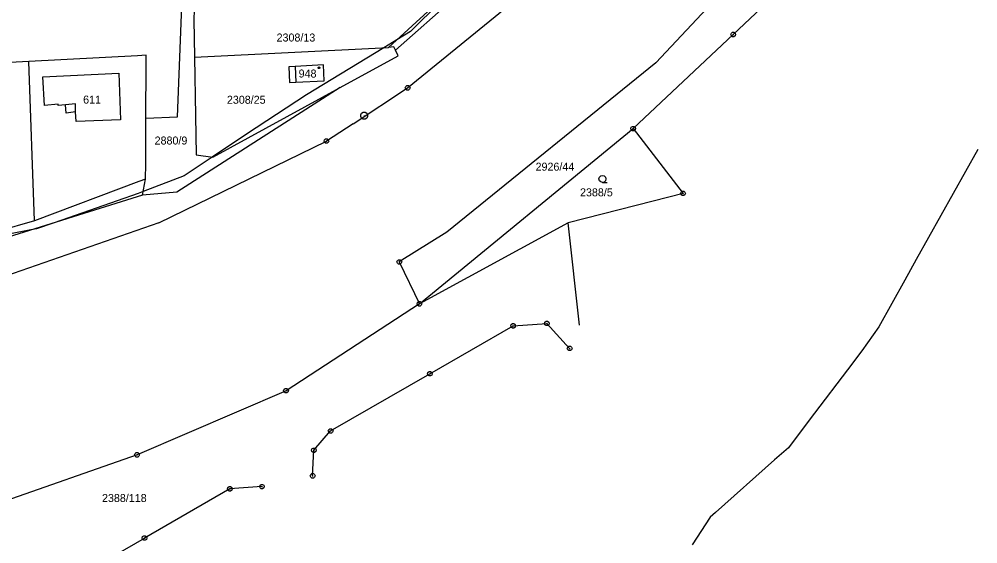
# Model space of a CAD drawing. Extents: x -760611 to -758411, y -1176479 to -1174807.
# Drawn here: x -758625.1 to -758421.5, y -1175039.9 to -1174928.5 of the extents above; entities that cross this region are included whole.
import ezdxf

# ---------------------------------------------------------------- set-up
doc = ezdxf.new("R2010")
doc.units = 0
for name, color, linetype in [('1', 7, 'Continuous'), ('11', 7, 'Continuous'), ('12', 7, 'Continuous'), ('2', 7, 'Continuous'), ('3', 7, 'Continuous'), ('4', 7, 'Continuous'), ('5', 7, 'Continuous'), ('8', 7, 'Continuous')]:
    doc.layers.add(name, color=color, linetype=linetype)

msp = doc.modelspace()

# ---------------------------------------------------------------- linework, layer by layer
at = {"layer": '1'}
for p, q in [((-758591.43, -1174949.22), (-758588.38, -1174867.67)), ((-758542.58, -1174943.09), (-758500.14, -1174908.44)), ((-758465.75, -1174911.99), (-758489.89, -1174937.8)), ((-758456.16, -1174915.41), (-758473.44, -1174931.75)), ((-758587.91, -1174926.56), (-758587.96, -1174928.54)), ((-758546.66, -1174934.51), (-758537.48, -1174926.06)), ((-758587.96, -1174928.54), (-758587.83, -1174936.54)), ((-758473.44, -1174931.75), (-758494.7, -1174951.75)), ((-758587.83, -1174936.54), (-758546.66, -1174934.51)), ((-758545.54, -1174934.37), (-758546.66, -1174934.51)), ((-758545.16, -1174935.1), (-758545.54, -1174934.37)), ((-758544.56, -1174936.26), (-758545.16, -1174935.1)), ((-758623.02, -1174937.49), (-758641.98, -1174938.52)), ((-758599.95, -1174936.27), (-758623.02, -1174937.49)), ((-758621.85, -1174971.3), (-758623.02, -1174937.49)), ((-758598.09, -1174936.17), (-758599.95, -1174936.27)), ((-758598.15, -1174949.55), (-758598.1, -1174938.09)), ((-758598.1, -1174938.09), (-758598.09, -1174936.17)), ((-758587.83, -1174936.54), (-758587.62, -1174949.03)), ((-758556.89, -1174943.02), (-758544.56, -1174936.26)), ((-758489.89, -1174937.8), (-758534.26, -1174973.76)), ((-758566.5, -1174938.54), (-758567.8, -1174938.61)), ((-758567.8, -1174938.61), (-758567.66, -1174941.96)), ((-758560.46, -1174938.22), (-758566.5, -1174938.54)), ((-758560.29, -1174941.57), (-758560.46, -1174938.22)), ((-758567.66, -1174941.96), (-758566.32, -1174941.89)), ((-758566.32, -1174941.89), (-758560.29, -1174941.57)), ((-758556.89, -1174943.02), (-758591.6, -1174965.21)), ((-758583.93, -1174957.84), (-758556.89, -1174943.02)), ((-758554.18, -1174950.69), (-758542.58, -1174943.09)), ((-758615.07, -1174948.44), (-758615.25, -1174946.66)), ((-758613.08, -1174948.19), (-758615.07, -1174948.44)), ((-758598.2, -1174959.24), (-758598.15, -1174949.55)), ((-758598.15, -1174949.55), (-758591.43, -1174949.22)), ((-758587.62, -1174949.03), (-758587.48, -1174957.31)), ((-758554.18, -1174950.69), (-758559.83, -1174954.39)), ((-758540.08, -1174988.98), (-758494.7, -1174951.75)), ((-758494.7, -1174951.75), (-758484.1, -1174965.51)), ((-758595.39, -1174971.76), (-758559.83, -1174954.39)), ((-758587.48, -1174957.31), (-758583.93, -1174957.84)), ((-758598.22, -1174962.46), (-758598.2, -1174959.24)), ((-758598.22, -1174962.46), (-758599.63, -1174962.98)), ((-758598.85, -1174965.89), (-758598.22, -1174962.46)), ((-758599.63, -1174962.98), (-758621.85, -1174971.3)), ((-758598.85, -1174965.89), (-758691.55, -1174994.68)), ((-758591.6, -1174965.21), (-758598.85, -1174965.89)), ((-758484.1, -1174965.51), (-758490.43, -1174967.13)), ((-758490.43, -1174967.13), (-758508.47, -1174971.76)), ((-758595.39, -1174971.76), (-758648.73, -1174990.25)), ((-758621.85, -1174971.3), (-758644.19, -1174977.86)), ((-758508.47, -1174971.76), (-758540.08, -1174988.98)), ((-758506.08, -1174993.49), (-758508.47, -1174971.76)), ((-758534.26, -1174973.76), (-758544.35, -1174980.07)), ((-758544.35, -1174980.07), (-758540.08, -1174988.98)), ((-758540.08, -1174988.98), (-758568.41, -1175007.42)), ((-758537.87, -1175003.83), (-758520.17, -1174993.64)), ((-758520.17, -1174993.64), (-758513.01, -1174993.13)), ((-758513.01, -1174993.13), (-758508.18, -1174998.44)), ((-758558.93, -1175015.96), (-758537.87, -1175003.83)), ((-758568.41, -1175007.42), (-758600.05, -1175021.05)), ((-758562.5, -1175020.07), (-758558.93, -1175015.96)), ((-758600.05, -1175021.05), (-758629.62, -1175031.39)), ((-758562.75, -1175025.5), (-758562.5, -1175020.07)), ((-758580.34, -1175028.28), (-758598.46, -1175038.72)), ((-758573.52, -1175027.8), (-758580.34, -1175028.28)), ((-758619.44, -1175050.8), (-758598.46, -1175038.72))]:
    msp.add_line(p, q, dxfattribs=at)
at = {"layer": '11'}
for points in [[(-758535.6, -1174924.8), (-758541.98, -1174931.12), (-758544.91, -1174932.9), (-758547.64, -1174934.56), (-758564.08, -1174944.55), (-758576.83, -1174952.95), (-758584.1, -1174957.81), (-758590.01, -1174961.77), (-758598.71, -1174965.12), (-758599.77, -1174965.53), (-758617.64, -1174971.72), (-758621.42, -1174973.04), (-758622.6, -1174973.27), (-758632.03, -1174975.1)], [(-758421.51, -1174956.21), (-758434.58, -1174979.55), (-758437.02, -1174983.92), (-758442.56, -1174993.82), (-758446.17, -1174998.98), (-758446.4, -1174999.3), (-758448.08, -1175001.51), (-758457.29, -1175013.66), (-758461.74, -1175019.53), (-758464.65, -1175022.12), (-758477.22, -1175033.28), (-758478.33, -1175034.26), (-758482.16, -1175040.17)]]:
    msp.add_lwpolyline(points, dxfattribs=at)
at = {"layer": '12'}
for p, q in [((-758620.02, -1174940.77), (-758603.93, -1174939.93)), ((-758603.93, -1174939.93), (-758603.54, -1174949.88)), ((-758560.46, -1174938.22), (-758566.5, -1174938.54)), ((-758566.5, -1174938.54), (-758566.32, -1174941.89)), ((-758560.29, -1174941.57), (-758560.46, -1174938.22)), ((-758619.7, -1174946.86), (-758620.02, -1174940.77)), ((-758566.32, -1174941.89), (-758560.29, -1174941.57)), ((-758616.8, -1174946.56), (-758619.7, -1174946.86)), ((-758616.77, -1174946.82), (-758616.8, -1174946.56)), ((-758615.25, -1174946.66), (-758616.77, -1174946.82)), ((-758613.14, -1174946.45), (-758615.25, -1174946.66)), ((-758613.08, -1174948.19), (-758613.14, -1174946.45)), ((-758613, -1174950.25), (-758613.08, -1174948.19)), ((-758603.54, -1174949.88), (-758613, -1174950.25))]:
    msp.add_line(p, q, dxfattribs=at)
at = {"layer": '3'}
msp.add_lwpolyline([(-758501.2, -1174963.17), (-758501.58, -1174963.07), (-758501.85, -1174962.8), (-758501.95, -1174962.43), (-758501.85, -1174962.06), (-758501.58, -1174961.79), (-758501.21, -1174961.69), (-758500.84, -1174961.79), (-758500.57, -1174962.06), (-758500.47, -1174962.44), (-758500.57, -1174962.82), (-758500.84, -1174963.09), (-758501.22, -1174963.19), (-758500.22, -1174963.19)], dxfattribs=at)
at = {"layer": '4'}
for p, q in [((-758509.23, -1174903.24), (-758545.16, -1174935.1)), ((-758566.5, -1174938.54), (-758566.32, -1174941.89))]:
    msp.add_line(p, q, dxfattribs=at)
at = {"layer": '5'}
msp.add_lwpolyline([(-758561.41, -1174938.65), (-758561.31, -1174938.67), (-758561.26, -1174938.76), (-758561.24, -1174938.82), (-758561.26, -1174938.91), (-758561.34, -1174938.98), (-758561.41, -1174938.99), (-758561.5, -1174938.96), (-758561.56, -1174938.9), (-758561.58, -1174938.82), (-758561.56, -1174938.73), (-758561.48, -1174938.66)], close=True, dxfattribs=at)
at = {"layer": '8'}
for p, q in [((-758473.56, -1174931.75), (-758473.32, -1174931.75)), ((-758542.7, -1174943.09), (-758542.46, -1174943.09)), ((-758551.86, -1174948.99), (-758551.76, -1174948.99)), ((-758494.82, -1174951.75), (-758494.58, -1174951.75)), ((-758559.95, -1174954.39), (-758559.71, -1174954.39)), ((-758484.22, -1174965.51), (-758483.98, -1174965.51)), ((-758544.47, -1174980.07), (-758544.23, -1174980.07)), ((-758540.2, -1174988.98), (-758539.96, -1174988.98)), ((-758520.29, -1174993.64), (-758520.05, -1174993.64)), ((-758513.13, -1174993.13), (-758512.89, -1174993.13)), ((-758508.3, -1174998.44), (-758508.06, -1174998.44)), ((-758537.99, -1175003.83), (-758537.75, -1175003.83)), ((-758568.53, -1175007.42), (-758568.29, -1175007.42)), ((-758568.53, -1175007.42), (-758568.29, -1175007.42)), ((-758568.53, -1175007.42), (-758568.29, -1175007.42)), ((-758559.05, -1175015.96), (-758558.81, -1175015.96)), ((-758600.17, -1175021.05), (-758599.93, -1175021.05)), ((-758562.62, -1175020.07), (-758562.38, -1175020.07)), ((-758562.87, -1175025.5), (-758562.63, -1175025.5)), ((-758580.46, -1175028.28), (-758580.22, -1175028.28)), ((-758573.64, -1175027.8), (-758573.4, -1175027.8)), ((-758598.58, -1175038.72), (-758598.34, -1175038.72))]:
    msp.add_line(p, q, dxfattribs=at)
for points in [[(-758473.29, -1174931.27), (-758473.04, -1174931.45), (-758472.94, -1174931.74), (-758473.04, -1174932.03), (-758473.29, -1174932.21), (-758473.6, -1174932.21), (-758473.85, -1174932.03), (-758473.95, -1174931.74), (-758473.85, -1174931.45), (-758473.6, -1174931.27)], [(-758542.43, -1174942.61), (-758542.18, -1174942.79), (-758542.08, -1174943.08), (-758542.18, -1174943.37), (-758542.43, -1174943.55), (-758542.74, -1174943.55), (-758542.99, -1174943.37), (-758543.09, -1174943.08), (-758542.99, -1174942.79), (-758542.74, -1174942.61)], [(-758551.62, -1174948.27), (-758551.28, -1174948.46), (-758551.09, -1174948.8), (-758551.09, -1174949.19), (-758551.28, -1174949.53), (-758551.62, -1174949.72), (-758552.01, -1174949.72), (-758552.35, -1174949.53), (-758552.54, -1174949.19), (-758552.54, -1174948.8), (-758552.35, -1174948.46), (-758552.01, -1174948.27)], [(-758494.55, -1174951.27), (-758494.3, -1174951.45), (-758494.2, -1174951.74), (-758494.3, -1174952.03), (-758494.55, -1174952.21), (-758494.86, -1174952.21), (-758495.11, -1174952.03), (-758495.21, -1174951.74), (-758495.11, -1174951.45), (-758494.86, -1174951.27)], [(-758559.68, -1174953.91), (-758559.43, -1174954.09), (-758559.33, -1174954.38), (-758559.43, -1174954.67), (-758559.68, -1174954.85), (-758559.99, -1174954.85), (-758560.24, -1174954.67), (-758560.34, -1174954.38), (-758560.24, -1174954.09), (-758559.99, -1174953.91)], [(-758483.95, -1174965.03), (-758483.7, -1174965.21), (-758483.6, -1174965.5), (-758483.7, -1174965.79), (-758483.95, -1174965.97), (-758484.26, -1174965.97), (-758484.51, -1174965.79), (-758484.61, -1174965.5), (-758484.51, -1174965.21), (-758484.26, -1174965.03)], [(-758544.2, -1174979.59), (-758543.95, -1174979.77), (-758543.85, -1174980.06), (-758543.95, -1174980.35), (-758544.2, -1174980.53), (-758544.51, -1174980.53), (-758544.76, -1174980.35), (-758544.86, -1174980.06), (-758544.76, -1174979.77), (-758544.51, -1174979.59)], [(-758539.93, -1174988.5), (-758539.68, -1174988.68), (-758539.58, -1174988.97), (-758539.68, -1174989.26), (-758539.93, -1174989.44), (-758540.24, -1174989.44), (-758540.49, -1174989.26), (-758540.59, -1174988.97), (-758540.49, -1174988.68), (-758540.24, -1174988.5)], [(-758512.86, -1174992.65), (-758512.61, -1174992.83), (-758512.51, -1174993.12), (-758512.61, -1174993.41), (-758512.86, -1174993.59), (-758513.17, -1174993.59), (-758513.42, -1174993.41), (-758513.52, -1174993.12), (-758513.42, -1174992.83), (-758513.17, -1174992.65)], [(-758520.02, -1174993.16), (-758519.77, -1174993.34), (-758519.67, -1174993.63), (-758519.77, -1174993.92), (-758520.02, -1174994.1), (-758520.33, -1174994.1), (-758520.58, -1174993.92), (-758520.68, -1174993.63), (-758520.58, -1174993.34), (-758520.33, -1174993.16)], [(-758508.03, -1174997.96), (-758507.78, -1174998.14), (-758507.68, -1174998.43), (-758507.78, -1174998.72), (-758508.03, -1174998.9), (-758508.34, -1174998.9), (-758508.59, -1174998.72), (-758508.69, -1174998.43), (-758508.59, -1174998.14), (-758508.34, -1174997.96)], [(-758537.72, -1175003.35), (-758537.47, -1175003.53), (-758537.37, -1175003.82), (-758537.47, -1175004.11), (-758537.72, -1175004.29), (-758538.03, -1175004.29), (-758538.28, -1175004.11), (-758538.38, -1175003.82), (-758538.28, -1175003.53), (-758538.03, -1175003.35)], [(-758568.26, -1175006.94), (-758568.01, -1175007.12), (-758567.91, -1175007.41), (-758568.01, -1175007.7), (-758568.26, -1175007.88), (-758568.57, -1175007.88), (-758568.82, -1175007.7), (-758568.92, -1175007.41), (-758568.82, -1175007.12), (-758568.57, -1175006.94)], [(-758568.26, -1175006.94), (-758568.01, -1175007.12), (-758567.91, -1175007.41), (-758568.01, -1175007.7), (-758568.26, -1175007.88), (-758568.57, -1175007.88), (-758568.82, -1175007.7), (-758568.92, -1175007.41), (-758568.82, -1175007.12), (-758568.57, -1175006.94)], [(-758568.26, -1175006.94), (-758568.01, -1175007.12), (-758567.91, -1175007.41), (-758568.01, -1175007.7), (-758568.26, -1175007.88), (-758568.57, -1175007.88), (-758568.82, -1175007.7), (-758568.92, -1175007.41), (-758568.82, -1175007.12), (-758568.57, -1175006.94)], [(-758558.78, -1175015.48), (-758558.53, -1175015.66), (-758558.43, -1175015.95), (-758558.53, -1175016.24), (-758558.78, -1175016.42), (-758559.09, -1175016.42), (-758559.34, -1175016.24), (-758559.44, -1175015.95), (-758559.34, -1175015.66), (-758559.09, -1175015.48)], [(-758599.9, -1175020.57), (-758599.65, -1175020.75), (-758599.55, -1175021.04), (-758599.65, -1175021.33), (-758599.9, -1175021.51), (-758600.21, -1175021.51), (-758600.46, -1175021.33), (-758600.56, -1175021.04), (-758600.46, -1175020.75), (-758600.21, -1175020.57)], [(-758562.35, -1175019.59), (-758562.1, -1175019.77), (-758562, -1175020.06), (-758562.1, -1175020.35), (-758562.35, -1175020.53), (-758562.66, -1175020.53), (-758562.91, -1175020.35), (-758563.01, -1175020.06), (-758562.91, -1175019.77), (-758562.66, -1175019.59)], [(-758562.6, -1175025.02), (-758562.35, -1175025.2), (-758562.25, -1175025.49), (-758562.35, -1175025.78), (-758562.6, -1175025.96), (-758562.91, -1175025.96), (-758563.16, -1175025.78), (-758563.26, -1175025.49), (-758563.16, -1175025.2), (-758562.91, -1175025.02)], [(-758573.37, -1175027.32), (-758573.12, -1175027.5), (-758573.02, -1175027.79), (-758573.12, -1175028.08), (-758573.37, -1175028.26), (-758573.68, -1175028.26), (-758573.93, -1175028.08), (-758574.03, -1175027.79), (-758573.93, -1175027.5), (-758573.68, -1175027.32)], [(-758580.19, -1175027.8), (-758579.94, -1175027.98), (-758579.84, -1175028.27), (-758579.94, -1175028.56), (-758580.19, -1175028.74), (-758580.5, -1175028.74), (-758580.75, -1175028.56), (-758580.85, -1175028.27), (-758580.75, -1175027.98), (-758580.5, -1175027.8)], [(-758598.31, -1175038.24), (-758598.06, -1175038.42), (-758597.96, -1175038.71), (-758598.06, -1175039), (-758598.31, -1175039.18), (-758598.62, -1175039.18), (-758598.87, -1175039), (-758598.97, -1175038.71), (-758598.87, -1175038.42), (-758598.62, -1175038.24)]]:
    msp.add_lwpolyline(points, close=True, dxfattribs=at)

# ---------------------------------------------------------------- texts
at = {"layer": '2'}
for s, p in [('2308/13', (-758570.41, -1174933.24)), ('948', (-758565.73, -1174940.89)), ('611', (-758611.49, -1174946.43)), ('2308/25', (-758580.96, -1174946.46)), ('2880/9', (-758596.31, -1174955.12)), ('2926/44', (-758515.42, -1174960.68)), ('2388/5', (-758505.98, -1174966.13)), ('2388/118', (-758607.48, -1175031.06))]:
    msp.add_text(s, height=1.7, dxfattribs=at).set_placement(p)

doc.saveas('drawing.dxf')
